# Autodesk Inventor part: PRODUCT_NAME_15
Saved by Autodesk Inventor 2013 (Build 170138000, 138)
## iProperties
Created: 2012-12
Part Number: PRODUCT_NAME_15
Material: Générique
Document SubType Name: Modeling
Designer: jost thierry
Density: 1 g/cm^3
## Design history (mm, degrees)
node "PRODUCT_NAME_151"
node "PRODUCT_NAME_15"
node "Base1"
